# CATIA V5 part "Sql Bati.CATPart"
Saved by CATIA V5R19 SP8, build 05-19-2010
Part number: Sql Bati
Publications: "Droite.1", "Plan.1", "Droite.2", "Droite.3"
Bounding box of the stored display mesh (mm): x 100 to 100, y 145 to 185, z -200 to 0
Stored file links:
  C:\Users\ThinkMotion\Desktop\EU_thinkMotion\iao\IAO_MMS_Groupe3\rdalborgo\rdalborgo\Sql Bati.CATPart
  C:\Users\ThinkMotion\Desktop\EU_thinkMotion\iao\IAO_MMS_Groupe3\rdalborgo\rdalborgo\Sql train.CATProduct
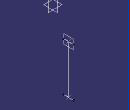
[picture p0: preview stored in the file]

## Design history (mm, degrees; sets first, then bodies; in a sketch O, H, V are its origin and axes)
Set1
  Point1 "A bati": linked copy from another document
  Point2 "D bati": linked copy from another document
  Plane1: linked copy from another document
  Plane2: linked copy from another document
Set2
  Line1: type PtPt, FirstPoint Point1, SecondPoint Point2
  Plane3: type OffsetPt, RefPlane Plane1, RefPoint Point1
  Line2: type Normal, RefPoint Point1, RefSkin Plane2, Start -20, End 20
  Line3: type Normal, RefPoint Point2, RefSkin Plane2, Start -20, End 20
Body1 (main body)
